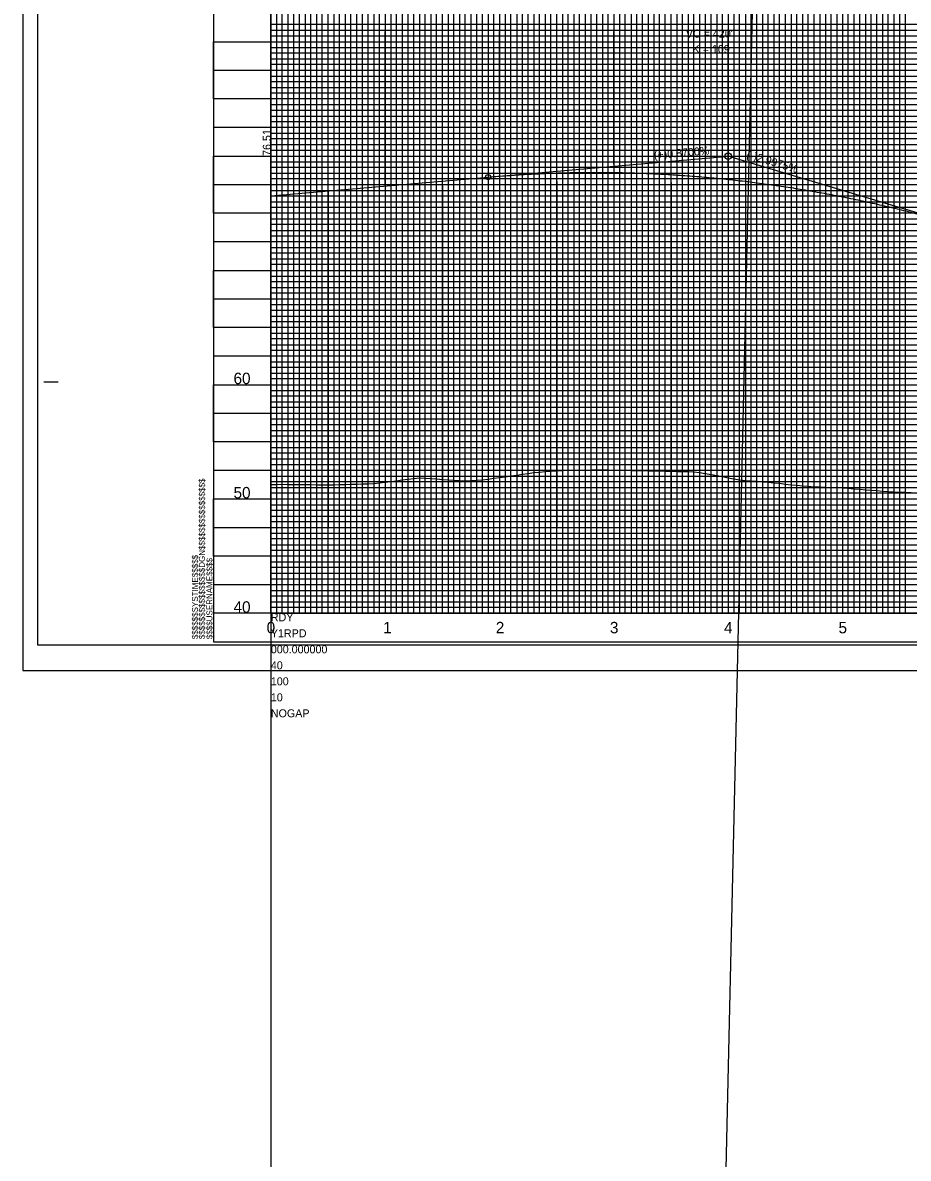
# Model space of a CAD drawing. Extents: x 2345490 to 2436403, y 465165 to 573888.
# Drawn here: x 2410678 to 2411453, y 502339 to 503333 of the extents above; entities that cross this region are included whole.
import ezdxf

# ---------------------------------------------------------------- set-up
doc = ezdxf.new("R2010")
doc.units = 0
for name, color, linetype in [('Old_Level_1', 7, 'Continuous'), ('Old_Level_18', 7, 'Continuous'), ('Old_Level_2', 7, 'Continuous'), ('Old_Level_40', 7, 'Continuous'), ('Old_Level_41', 7, 'Continuous'), ('Old_Level_42', 7, 'Continuous'), ('Old_Level_43', 7, 'Continuous'), ('Old_Level_50', 7, 'Continuous'), ('Old_Level_51', 7, 'Continuous'), ('Old_Level_52', 7, 'Continuous'), ('Old_Level_63', 7, 'Continuous')]:
    doc.layers.add(name, color=color, linetype=linetype)

msp = doc.modelspace()

# ---------------------------------------------------------------- linework, layer by layer
at = {"layer": 'Old_Level_1'}
for points in [[(2410895.325, 502928.70725), (2410900.325, 502928.78825), (2410905.325, 502928.84575), (2410910.325, 502928.798), (2410915.325, 502928.73675), (2410920.325, 502928.67525), (2410925.325, 502928.614), (2410930.325, 502928.5525), (2410935.325, 502928.491), (2410940.325, 502928.42975), (2410945.325, 502928.36825), (2410950.325, 502928.4735), (2410955.325, 502928.6195), (2410960.325, 502928.76525), (2410965.325, 502928.91125), (2410970.325, 502929.05725), (2410975.325, 502929.203), (2410980.325, 502929.35225), (2410985.325, 502929.5075), (2410990.325, 502930.0425), (2410995.325, 502930.682), (2411000.325, 502931.32125), (2411005.325, 502931.96075), (2411010.325, 502932.6), (2411015.325, 502933.2395), (2411020.325, 502933.807), (2411025.325, 502934.363), (2411030.325, 502934.21875), (2411035.325, 502933.85925), (2411040.325, 502933.49975), (2411045.325, 502933.14), (2411050.325, 502932.7805), (2411055.325, 502932.458), (2411060.325, 502932.2), (2411065.325, 502931.94225), (2411070.325, 502932.1425), (2411075.325, 502932.499), (2411080.325, 502932.8555), (2411085.325, 502933.454), (2411090.325, 502934.13), (2411095.325, 502934.806), (2411100.325, 502935.48175), (2411105.325, 502936.157), (2411110.325, 502936.88775), (2411115.325, 502937.63725), (2411120.325, 502938.3865), (2411125.325, 502939.1055), (2411130.325, 502939.51525), (2411135.325, 502939.925), (2411140.325, 502940.3345), (2411145.325, 502940.74425), (2411150.325, 502940.94225), (2411155.325, 502941.04975), (2411160.325, 502941.15725), (2411165.325, 502941.2645), (2411170.325, 502941.306), (2411175.325, 502941.3475), (2411180.325, 502941.389), (2411185.325, 502941.43025), (2411190.325, 502941.38025), (2411195.325, 502941.2835), (2411200.325, 502941.18675), (2411205.325, 502941.08275), (2411210.325, 502940.97625), (2411215.325, 502940.86975), (2411220.325, 502940.76325), (2411225.325, 502940.6565), (2411230.325, 502940.58575), (2411235.325, 502940.539), (2411240.325, 502940.43475), (2411245.325, 502940.29825), (2411250.325, 502940.1615), (2411255.325, 502940.024), (2411260.325, 502939.88625), (2411265.325, 502939.748), (2411270.325, 502939.16325), (2411275.325, 502938.2385), (2411280.325, 502937.36375), (2411285.325, 502936.49), (2411290.325, 502935.61775), (2411295.325, 502934.6175), (2411300.325, 502933.61025), (2411305.325, 502932.60075), (2411310.325, 502932.2555), (2411315.325, 502931.848), (2411320.325, 502931.441), (2411325.325, 502931.035), (2411330.325, 502930.6295), (2411335.325, 502930.22475), (2411340.325, 502929.71725), (2411345.325, 502929.0645), (2411350.325, 502928.417), (2411355.325, 502927.9905), (2411360.325, 502927.5635), (2411365.325, 502927.136), (2411370.325, 502926.70825), (2411375.325, 502926.52125), (2411380.325, 502926.33675), (2411385.325, 502926.15275), (2411390.325, 502925.969), (2411395.325, 502925.70625)], [(2411395.325, 502925.70625), (2411400.325, 502925.395), (2411405.325, 502924.99775), (2411410.325, 502924.56325), (2411415.325, 502924.12875), (2411420.325, 502923.695), (2411425.325, 502923.26125), (2411430.325, 502922.83775), (2411435.325, 502922.45075), (2411440.325, 502922.24725), (2411445.325, 502922.044), (2411450.325, 502921.841), (2411455.325, 502921.6385)]]:
    msp.add_lwpolyline(points, dxfattribs=at)
at = {"layer": 'Old_Level_18'}
msp.add_line((2410845.325, 502790.981), (2410845.325, 502790.981), dxfattribs=at)
msp.add_line((2410845.325, 502790.981), (2410845.325, 502790.981), dxfattribs=at)
msp.add_lwpolyline([(2412345.325, 503840.981), (2410845.325, 503840.981), (2410845.325, 502790.981), (2412345.325, 502790.981)], close=True, dxfattribs=at)
at = {"layer": 'Old_Level_2'}
for p, q in [((2411722.59175, 521117.51825), (2411239.1575, 499960.77)), ((2410895.325, 503380.881), (2410895.325, 503181.081)), ((2411085.325, 503197.611), (2411292.5855, 503215.64275)), ((2411505.325, 503152.9335), (2411297.95925, 503215.0915)), ((2410895.325, 503181.081), (2411085.325, 503197.611))]:
    msp.add_line(p, q, dxfattribs=at)
for centre, radius in [((2411295.325, 503215.881), 2.75), ((2411085.325, 503197.611), 2.25)]:
    msp.add_circle(centre, radius, dxfattribs=at)
msp.add_spline([(2411085.325, 503197.611), (2411093.725, 503198.3095), (2411102.125, 503198.94275), (2411110.525, 503199.51125), (2411118.925, 503200.0145), (2411127.325, 503200.453), (2411135.725, 503200.8265), (2411144.125, 503201.13475), (2411152.525, 503201.37825), (2411160.925, 503201.557), (2411169.325, 503201.6705), (2411177.725, 503201.719), (2411186.125, 503201.7025), (2411194.525, 503201.62125), (2411202.925, 503201.47475), (2411211.325, 503201.2635), (2411219.725, 503200.98725), (2411228.125, 503200.646), (2411236.525, 503200.23975), (2411244.925, 503199.7685), (2411253.325, 503199.23225), (2411261.725, 503198.63125), (2411270.125, 503197.965), (2411278.525, 503197.234), (2411286.925, 503196.43775), (2411295.325, 503195.57675), (2411303.725, 503194.65075), (2411312.125, 503193.65975), (2411320.525, 503192.60375), (2411328.925, 503191.48275), (2411337.325, 503190.29675), (2411345.725, 503189.046), (2411354.125, 503187.73), (2411362.525, 503186.34925), (2411370.925, 503184.90325), (2411379.325, 503183.3925), (2411387.725, 503181.81675), (2411396.125, 503180.176), (2411404.525, 503178.47025), (2411412.925, 503176.6995), (2411421.325, 503174.864), (2411429.725, 503172.96325), (2411438.125, 503170.99775), (2411446.525, 503168.967), (2411454.925, 503166.8715), (2411463.325, 503164.711), (2411471.725, 503162.4855), (2411480.125, 503160.195), (2411488.525, 503157.8395), (2411496.925, 503155.419), (2411505.325, 503152.9335)], degree=3, dxfattribs=at)
at = {"layer": 'Old_Level_40'}
msp.add_line((2410845.325, 502790.981), (2410845.325, 502790.981), dxfattribs=at)
msp.add_line((2410845.325, 502790.981), (2410845.325, 502790.981), dxfattribs=at)
msp.add_line((2410845.325, 502790.981), (2410845.325, 502790.981), dxfattribs=at)
msp.add_line((2410845.325, 502790.981), (2410845.325, 502790.981), dxfattribs=at)
at = {"layer": 'Old_Level_41'}
for p, q in [((2410696.825, 503018.481), (2410709.325, 503018.481)), ((2412345.325, 502815.981), (2410845.325, 502815.981))]:
    msp.add_line(p, q, dxfattribs=at)
for points in [[(2410895.325, 503840.981), (2410895.325, 502815.981), (2410945.325, 502815.981), (2410945.325, 503840.981)], [(2410920.325, 502815.981), (2410920.325, 503840.981)], [(2410970.325, 503840.981), (2410970.325, 502815.981), (2411020.325, 502815.981), (2411020.325, 503840.981)], [(2410995.325, 503840.981), (2410995.325, 502815.981), (2411045.325, 502815.981), (2411045.325, 503840.981)], [(2411070.325, 503840.981), (2411070.325, 502815.981), (2411120.325, 502815.981), (2411120.325, 503840.981)], [(2411095.325, 503840.981), (2411095.325, 502815.981), (2411145.325, 502815.981), (2411145.325, 503840.981)], [(2411170.325, 503840.981), (2411170.325, 502815.981), (2411220.325, 502815.981), (2411220.325, 503840.981)], [(2411195.325, 503840.981), (2411195.325, 502815.981), (2411245.325, 502815.981), (2411245.325, 503840.981)], [(2411270.325, 503840.981), (2411270.325, 502815.981), (2411320.325, 502815.981), (2411320.325, 503840.981)], [(2411295.325, 503840.981), (2411295.325, 502815.981), (2411345.325, 502815.981), (2411345.325, 503840.981)], [(2411370.325, 503840.981), (2411370.325, 502815.981), (2411420.325, 502815.981), (2411420.325, 503840.981)], [(2411395.325, 503840.981), (2411395.325, 502815.981), (2411445.325, 502815.981), (2411445.325, 503840.981)], [(2412345.325, 503340.981), (2410845.325, 503340.981), (2410845.325, 503290.981), (2412345.325, 503290.981)], [(2412345.325, 503240.981), (2410845.325, 503240.981), (2410845.325, 503190.981), (2412345.325, 503190.981)], [(2412345.325, 503165.981), (2410845.325, 503165.981), (2410845.325, 503215.981), (2412345.325, 503215.981)], [(2412345.325, 503140.981), (2410845.325, 503140.981), (2410845.325, 503090.981), (2412345.325, 503090.981)], [(2412345.325, 503065.981), (2410845.325, 503065.981), (2410845.325, 503115.981), (2412345.325, 503115.981)], [(2412345.325, 503040.981), (2410845.325, 503040.981), (2410845.325, 502990.981), (2412345.325, 502990.981)], [(2412345.325, 502940.981), (2410845.325, 502940.981), (2410845.325, 502890.981), (2412345.325, 502890.981)], [(2412345.325, 502865.981), (2410845.325, 502865.981), (2410845.325, 502915.981), (2412345.325, 502915.981)], [(2412345.325, 502840.981), (2410845.325, 502840.981)], [(2410882.825, 502790.981), (2410882.825, 502790.981)]]:
    msp.add_lwpolyline(points, dxfattribs=at)
at = {"layer": 'Old_Level_42'}
for points in [[(2412345.325, 503265.981), (2410845.325, 503265.981), (2410845.325, 503315.981), (2412345.325, 503315.981)], [(2412345.325, 502965.981), (2410845.325, 502965.981), (2410845.325, 503015.981), (2412345.325, 503015.981)]]:
    msp.add_lwpolyline(points, dxfattribs=at)
at = {"layer": 'Old_Level_43'}
for points in [[(2410900.325, 503840.981), (2410900.325, 502815.981), (2410905.325, 502815.981), (2410905.325, 503840.981)], [(2410910.325, 503840.981), (2410910.325, 502815.981), (2410915.325, 502815.981), (2410915.325, 503840.981)], [(2410925.325, 503840.981), (2410925.325, 502815.981), (2410930.325, 502815.981), (2410930.325, 503840.981)], [(2410935.325, 503840.981), (2410935.325, 502815.981), (2410940.325, 502815.981), (2410940.325, 503840.981)], [(2410950.325, 503840.981), (2410950.325, 502815.981), (2410955.325, 502815.981), (2410955.325, 503840.981)], [(2410960.325, 503840.981), (2410960.325, 502815.981), (2410965.325, 502815.981), (2410965.325, 503840.981)], [(2410975.325, 503840.981), (2410975.325, 502815.981), (2410980.325, 502815.981), (2410980.325, 503840.981)], [(2410985.325, 503840.981), (2410985.325, 502815.981), (2410990.325, 502815.981), (2410990.325, 503840.981)], [(2411000.325, 503840.981), (2411000.325, 502815.981), (2411005.325, 502815.981), (2411005.325, 503840.981)], [(2411010.325, 503840.981), (2411010.325, 502815.981), (2411015.325, 502815.981), (2411015.325, 503840.981)], [(2411025.325, 503840.981), (2411025.325, 502815.981), (2411030.325, 502815.981), (2411030.325, 503840.981)], [(2411035.325, 503840.981), (2411035.325, 502815.981), (2411040.325, 502815.981), (2411040.325, 503840.981)], [(2411050.325, 503840.981), (2411050.325, 502815.981), (2411055.325, 502815.981), (2411055.325, 503840.981)], [(2411060.325, 502815.981), (2411065.325, 502815.981), (2411065.325, 503840.981)], [(2411060.325, 503840.981), (2411060.325, 502815.981)], [(2411075.325, 503840.981), (2411075.325, 502815.981), (2411080.325, 502815.981), (2411080.325, 503840.981)], [(2411085.325, 503840.981), (2411085.325, 502815.981), (2411090.325, 502815.981), (2411090.325, 503840.981)], [(2411100.325, 503840.981), (2411100.325, 502815.981), (2411105.325, 502815.981), (2411105.325, 503840.981)], [(2411110.325, 503840.981), (2411110.325, 502815.981), (2411115.325, 502815.981), (2411115.325, 503840.981)], [(2411125.325, 503840.981), (2411125.325, 502815.981), (2411130.325, 502815.981), (2411130.325, 503840.981)], [(2411135.325, 503840.981), (2411135.325, 502815.981), (2411140.325, 502815.981), (2411140.325, 503840.981)], [(2411150.325, 503840.981), (2411150.325, 502815.981), (2411155.325, 502815.981), (2411155.325, 503840.981)], [(2411160.325, 503840.981), (2411160.325, 502815.981), (2411165.325, 502815.981), (2411165.325, 503840.981)], [(2411175.325, 503840.981), (2411175.325, 502815.981), (2411180.325, 502815.981), (2411180.325, 503840.981)], [(2411185.325, 503840.981), (2411185.325, 502815.981), (2411190.325, 502815.981), (2411190.325, 503840.981)], [(2411200.325, 503840.981), (2411200.325, 502815.981), (2411205.325, 502815.981), (2411205.325, 503840.981)], [(2411210.325, 503840.981), (2411210.325, 502815.981), (2411215.325, 502815.981), (2411215.325, 503840.981)], [(2411225.325, 503840.981), (2411225.325, 502815.981), (2411240.325, 502815.981), (2411240.325, 503840.981)], [(2411230.325, 503840.981), (2411230.325, 502815.981), (2411235.325, 502815.981), (2411235.325, 503840.981)], [(2411230.325, 503840.381), (2411230.325, 502815.981), (2411235.325, 502815.981), (2411235.325, 503840.381)], [(2411250.325, 503840.981), (2411250.325, 502815.981), (2411255.325, 502815.981), (2411255.325, 503840.981)], [(2411260.325, 503840.981), (2411260.325, 502815.981), (2411265.325, 502815.981), (2411265.325, 503840.981)], [(2411275.325, 503840.981), (2411275.325, 502815.981), (2411280.325, 502815.981), (2411280.325, 503840.981)], [(2411285.325, 503840.981), (2411285.325, 502815.981), (2411290.325, 502815.981), (2411290.325, 503840.981)], [(2411300.325, 503840.981), (2411300.325, 502815.981), (2411305.325, 502815.981), (2411305.325, 503840.981)], [(2411310.325, 503840.981), (2411310.325, 502815.981), (2411315.325, 502815.981), (2411315.325, 503840.981)], [(2411325.325, 503840.981), (2411325.325, 502815.981), (2411330.325, 502815.981), (2411330.325, 503840.981)], [(2411335.325, 503840.981), (2411335.325, 502815.981), (2411340.325, 502815.981), (2411340.325, 503840.981)], [(2411350.325, 503840.981), (2411350.325, 502815.981), (2411355.325, 502815.981), (2411355.325, 503840.981)], [(2411360.325, 503840.981), (2411360.325, 502815.981), (2411365.325, 502815.981), (2411365.325, 503840.981)], [(2411375.325, 503840.981), (2411375.325, 502815.981)], [(2411380.325, 503840.981), (2411380.325, 502815.981), (2411385.325, 502815.981), (2411385.325, 503840.981), (2411390.325, 503840.981), (2411390.325, 502815.981), (2411400.325, 502815.981), (2411400.325, 503840.981), (2411405.325, 503840.981), (2411405.325, 502815.981), (2411410.325, 502815.981), (2411410.325, 503840.981), (2411415.325, 503840.981), (2411415.325, 502815.981)], [(2411425.325, 502815.981), (2411425.325, 503840.981)], [(2411430.325, 503840.981), (2411430.325, 502815.981), (2411435.325, 502815.981), (2411435.325, 503840.981)], [(2411440.325, 503840.981), (2411440.325, 502815.981), (2411450.325, 502815.981), (2411450.325, 503840.981)], [(2412295.325, 503330.981), (2410895.325, 503330.981), (2410895.325, 503325.981), (2412295.325, 503325.981)], [(2412295.325, 503320.981), (2410895.325, 503320.981)], [(2410895.325, 503310.981), (2412295.325, 503310.981)], [(2412295.325, 503305.981), (2410895.325, 503305.981), (2410895.325, 503300.981), (2412295.325, 503300.981)], [(2412295.325, 503295.981), (2410895.325, 503295.981), (2410895.325, 503285.981), (2412295.325, 503285.981)], [(2412295.325, 503280.981), (2410895.325, 503280.981), (2410895.325, 503275.981), (2412295.325, 503275.981)], [(2412295.325, 503270.981), (2410895.325, 503270.981), (2410895.325, 503260.981), (2412295.325, 503260.981)], [(2412295.325, 503255.981), (2410895.325, 503255.981), (2410895.325, 503250.981), (2412295.325, 503250.981)], [(2412295.325, 503245.981), (2410895.325, 503245.981), (2410895.325, 503235.981), (2412295.325, 503235.981)], [(2412295.325, 503230.981), (2410895.325, 503230.981), (2410895.325, 503225.981), (2412295.325, 503225.981)], [(2412295.325, 503220.981), (2410895.325, 503220.981), (2410895.325, 503210.981), (2412295.325, 503210.981)], [(2412295.325, 503205.981), (2410895.325, 503205.981), (2410895.325, 503200.981), (2412295.325, 503200.981)], [(2412295.325, 503195.981), (2410895.325, 503195.981), (2410895.325, 503185.981), (2412295.325, 503185.981)], [(2412295.325, 503180.981), (2410895.325, 503180.981), (2410895.325, 503175.981), (2412295.325, 503175.981)], [(2412295.325, 503170.981), (2410895.325, 503170.981), (2410895.325, 503160.981), (2412295.325, 503160.981)], [(2412295.325, 503155.981), (2410895.325, 503155.981), (2410895.325, 503150.981), (2412295.325, 503150.981)], [(2412295.325, 503145.981), (2410895.325, 503145.981), (2410895.325, 503135.981), (2412295.325, 503135.981)], [(2412295.325, 503130.981), (2410895.325, 503130.981), (2410895.325, 503125.981), (2412295.325, 503125.981)], [(2412295.325, 503120.981), (2410895.325, 503120.981), (2410895.325, 503110.981), (2412295.325, 503110.981)], [(2412295.325, 503105.981), (2410895.325, 503105.981), (2410895.325, 503100.981), (2412295.325, 503100.981)], [(2412295.325, 503095.981), (2410895.325, 503095.981), (2410895.325, 503085.981), (2412295.325, 503085.981)], [(2412295.325, 503080.981), (2410895.325, 503080.981), (2410895.325, 503075.981), (2412295.325, 503075.981)], [(2412295.325, 503070.981), (2410895.325, 503070.981), (2410895.325, 503060.981), (2412295.325, 503060.981)], [(2412295.325, 503055.981), (2410895.325, 503055.981), (2410895.325, 503050.981), (2412295.325, 503050.981)], [(2412295.325, 503045.981), (2410895.325, 503045.981), (2410895.325, 503035.981), (2412295.325, 503035.981)], [(2412295.325, 503030.981), (2410895.325, 503030.981), (2410895.325, 503025.981), (2412295.325, 503025.981)], [(2412295.325, 503020.981), (2410895.325, 503020.981)], [(2410895.325, 503010.981), (2412295.325, 503010.981)], [(2412295.325, 503005.981), (2410895.325, 503005.981), (2410895.325, 503000.981), (2412295.325, 503000.981)], [(2412295.325, 502995.981), (2410895.325, 502995.981)], [(2410895.325, 502985.981), (2412295.325, 502985.981)], [(2412295.325, 502980.981), (2410895.325, 502980.981), (2410895.325, 502975.981), (2412295.325, 502975.981)], [(2412295.325, 502970.981), (2410895.325, 502970.981), (2410895.325, 502960.981), (2412295.325, 502960.981)], [(2412295.325, 502955.981), (2410895.325, 502955.981), (2410895.325, 502950.981), (2412295.325, 502950.981)], [(2412295.325, 502945.981), (2410895.325, 502945.981), (2410895.325, 502935.981), (2412295.325, 502935.981)], [(2412295.325, 502930.981), (2410895.325, 502930.981), (2410895.325, 502925.981), (2412295.325, 502925.981)], [(2412295.325, 502920.981), (2410895.325, 502920.981), (2410895.325, 502910.981), (2412295.325, 502910.981)], [(2412295.325, 502905.981), (2410895.325, 502905.981), (2410895.325, 502900.981), (2412295.325, 502900.981)], [(2412295.325, 502895.981), (2410895.325, 502895.981), (2410895.325, 502885.981), (2412295.325, 502885.981)], [(2412295.325, 502880.981), (2410895.325, 502880.981), (2410895.325, 502875.981), (2412295.325, 502875.981)], [(2412295.325, 502870.981), (2410895.325, 502870.981), (2410895.325, 502860.981), (2412295.325, 502860.981)], [(2412295.325, 502855.981), (2410895.325, 502855.981), (2410895.325, 502850.981), (2412295.325, 502850.981)], [(2412295.325, 502845.981), (2410895.325, 502845.981), (2410895.325, 502835.981), (2412295.325, 502835.981)], [(2412295.325, 502830.981), (2410895.325, 502830.981), (2410895.325, 502825.981), (2412295.325, 502825.981)], [(2412295.325, 502820.981), (2410895.325, 502820.981)]]:
    msp.add_lwpolyline(points, dxfattribs=at)
at = {"layer": 'Old_Level_50'}
msp.add_line((2410678.325, 502765.981), (2410678.325, 502765.981), dxfattribs=at)
msp.add_lwpolyline([(2412357.825, 503843.531), (2410691.325, 503843.531), (2410691.325, 502788.431), (2412357.825, 502788.431)], close=True, dxfattribs=at)
at = {"layer": 'Old_Level_51'}
msp.add_lwpolyline([(2412362.325, 503865.981), (2410678.325, 503865.981), (2410678.325, 502765.981), (2412362.325, 502765.981)], close=True, dxfattribs=at)
at = {"layer": 'Old_Level_52'}
msp.add_line((2410691.325, 502788.431), (2410691.325, 502788.431), dxfattribs=at)
at = {"layer": 'Old_Level_63'}
for p, q in [((2410895.325, 502815.981), (2410895.325, 505315.981)), ((2410995.325, 503191.021), (2410995.325, 503324.81125)), ((2411045.325, 503196.751), (2411045.325, 503324.81125)), ((2411095.325, 503202.481), (2411095.325, 503324.81125)), ((2411145.325, 503207.571), (2411145.325, 503324.81125)), ((2411195.325, 503208.771), (2411195.325, 503324.81125)), ((2411245.325, 503207.561), (2411245.325, 503324.81125)), ((2411295.325, 503206.111), (2411295.325, 503324.81125)), ((2411095.325, 503192.101), (2411095.325, 502890.3625)), ((2411145.325, 503193.771), (2411145.325, 502890.3625)), ((2411195.325, 503193.981), (2411195.325, 502890.3625)), ((2411245.325, 503192.751), (2411245.325, 502890.3625)), ((2410895.325, 503181.081), (2410895.325, 502890.3625)), ((2410945.325, 503185.431), (2410945.325, 502890.3625)), ((2410995.325, 503187.831), (2410995.325, 502890.3625)), ((2411045.325, 503189.971), (2411045.325, 502890.3625)), ((2411295.325, 503189.881), (2411295.325, 502890.3625)), ((2410895.325, 502815.981), (2412874.915, 502815.981)), ((2410895.325, 502815.981), (2410895.325, 500315.981))]:
    msp.add_line(p, q, dxfattribs=at)

# ---------------------------------------------------------------- texts
at = {"layer": 'Old_Level_1'}
for s, height, p in [('60', 10.000001, (2410862.7115, 503016.481)), ('50', 10.000001, (2410862.7115, 502916.481)), ('40', 10.000001, (2410862.7115, 502816.481)), ('0', 10, (2410891.666, 502798.481)), ('1', 10, (2410993.5055, 502798.481)), ('2', 10, (2411092.054, 502798.481)), ('3', 10, (2411191.88875, 502798.481)), ('4', 10, (2411291.731, 502798.481)), ('5', 10, (2411391.8235, 502798.481))]:
    msp.add_text(s, height=height, dxfattribs=at).set_placement(p)
at = {"layer": 'Old_Level_2'}
for s, p in [("VC = 420'", (2411258.26775, 503319.67775)), ('K = 109', (2411264.1735, 503306.10225))]:
    msp.add_text(s, height=7.000001, dxfattribs=at).set_placement(p)
for s, rotation, p in [('76.51', 90, (2410895.325, 503216.081)), ('(+)0.8700%', 4.97221389, (2411230.61925, 503213.263)), ('(-)2.9975%', 343.31389722, (2411310.7475, 503214.39025))]:
    msp.add_text(s, height=7.000001, rotation=rotation, dxfattribs=at).set_placement(p)
at = {"layer": 'Old_Level_41'}
for s, p in [('$$$$$$$$$$$$$$$$DGN$$$$$$$$$$$$$$$$', (2410837.675, 502793.3435)), ('$$$$$$SYSTIME$$$$$', (2410831.625, 502793.3435)), ('$$$$USERNAME$$$$', (2410844.25, 502793.356))]:
    msp.add_text(s, height=5.25, rotation=90, dxfattribs=at).set_placement(p)
at = {"layer": 'Old_Level_63'}
for s, p in [('RDY', (2410895.325, 502808.981)), ('Y1RPD', (2410895.325, 502794.981)), ('000.000000', (2410895.325, 502780.981)), ('40', (2410895.325, 502766.981)), ('100', (2410895.325, 502752.981)), ('10', (2410895.325, 502738.981)), ('NOGAP', (2410895.325, 502724.981))]:
    msp.add_text(s, height=7.000001, dxfattribs=at).set_placement(p)

doc.saveas('drawing.dxf')
